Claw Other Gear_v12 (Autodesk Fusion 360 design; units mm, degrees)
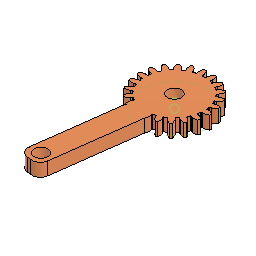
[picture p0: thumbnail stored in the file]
description: Spur Gear; Module: 0.7; Num Teeth: 22; Pressure Angle: 20.0; Backlash: 0.00 mm
sketch "Sketch1" plane through (0, 0, 0) normal (0, 0, 1) x axis (1, 0, 0)
  circle C1 centre (0, 0) radius 6.8092
  circle C2 centre (0, 0) radius 1.6
  dimension "d104" diameter C2 = 3.2
extrude "Extrude1" new body sketch "Sketch1" along normal blind 3
sketch "Sketch2" plane through (0, 0, 0) normal (0, 0, 1) x axis (1, 0, 0)
  curve K1 (8.3964, -0.2471) -> (7.2087, -0.6237)
  curve K2 (8.3964, 0.2471) -> (7.2087, 0.6237)
  line L1 (7.2087, -0.6237) -> (6.7739, -0.5869)
  line L2 (7.2087, 0.6237) -> (6.7739, 0.5869)
  line L3 (6.7739, 0.5869) -> (6.7739, -0.5869)
  arc A1 centre (0, 0) radius 8.4 clockwise from (8.3964, 0.2471) to (8.3964, -0.2471)
extrude "Extrude2" add sketch "Sketch2" along normal blind 3
fillet "Fillet1" radius 0.1
circular_pattern "C-Pattern1" countU 22 TotalAngle 360
sketch "Sketch3" plane through (0, 0, 0) normal (0, 0, 1) x axis (1, 0, 0)
  circle C1 centre (0, 0) radius 7.7
sketch "Sketch5" plane through (0, 0, 3) normal (0, 0, 1) x axis (-1, 0, 0)
  line L1 (-7.2087, 0.6237) -> (-6.8825, 0.5961)
  curve K1 (-8.3964, 0.2471) -> (-7.2087, 0.6237)
  curve K2 (-7.2087, -0.6237) -> (-8.3964, -0.2471)
  line L2 (-6.8825, -0.5961) -> (-7.2087, -0.6237)
  line L3 (-7.0924, -1.4325) -> (-6.7717, -1.3671)
  curve K3 (-8.1259, -2.1285) -> (-7.0924, -1.4325)
  curve K4 (-6.741, -2.6294) -> (-7.9866, -2.6026)
  line L4 (-6.4358, -2.511) -> (-6.741, -2.6294)
  line L5 (-6.4015, -3.3726) -> (-6.1122, -3.2195)
  curve K5 (-7.197, -4.3316) -> (-6.4015, -3.3726)
  curve K6 (-5.7272, -4.422) -> (-6.9299, -4.7473)
  line L6 (-5.4676, -4.2224) -> (-5.7272, -4.422)
  line L7 (-5.1921, -5.0395) -> (-4.9576, -4.8111)
  curve K7 (-5.6852, -6.1838) -> (-5.1921, -5.0395)
  curve K8 (-4.2493, -5.8564) -> (-5.3117, -6.5073)
  line L8 (-4.0566, -5.5918) -> (-4.2493, -5.8564)
  line L9 (-3.5619, -6.2982) -> (-3.4013, -6.0129)
  curve K9 (-3.7127, -7.535) -> (-3.5619, -6.2982)
  curve K10 (-2.4273, -6.8164) -> (-3.2632, -7.7402)
  line L10 (-2.3168, -6.5082) -> (-2.4273, -6.8164)
  line L11 (-1.6432, -7.0466) -> (-1.5695, -6.7276)
  curve K11 (-1.4395, -8.2757) -> (-1.6432, -7.0466)
  curve K12 (-0.4086, -7.2241) -> (-0.9504, -8.3461)
  line L12 (-0.3894, -6.8973) -> (-0.4086, -7.2241)
  line L13 (0.4086, -7.2241) -> (0.3894, -6.8973)
  curve K13 (0.9504, -8.3461) -> (0.4086, -7.2241)
  curve K14 (1.6432, -7.0466) -> (1.4395, -8.2757)
  line L14 (1.5695, -6.7276) -> (1.6432, -7.0466)
  line L15 (2.4273, -6.8164) -> (2.3168, -6.5082)
  curve K15 (3.2632, -7.7402) -> (2.4273, -6.8164)
  curve K16 (3.5619, -6.2982) -> (3.7127, -7.535)
  line L16 (3.4013, -6.0129) -> (3.5619, -6.2982)
  line L17 (4.2493, -5.8564) -> (4.0566, -5.5918)
  curve K17 (5.3117, -6.5073) -> (4.2493, -5.8564)
  curve K18 (5.1921, -5.0395) -> (5.6852, -6.1838)
  line L18 (4.9576, -4.8111) -> (5.1921, -5.0395)
  line L19 (5.7272, -4.422) -> (5.4676, -4.2224)
  curve K19 (6.9299, -4.7473) -> (5.7272, -4.422)
  curve K20 (6.4015, -3.3726) -> (7.197, -4.3316)
  line L20 (6.1122, -3.2195) -> (6.4015, -3.3726)
  line L21 (6.741, -2.6294) -> (6.4358, -2.511)
  curve K21 (7.9866, -2.6026) -> (6.741, -2.6294)
  curve K22 (7.0924, -1.4325) -> (8.1259, -2.1285)
  line L22 (6.7717, -1.3671) -> (7.0924, -1.4325)
  line L23 (7.2087, -0.6237) -> (6.8825, -0.5961)
  curve K23 (8.3964, -0.2471) -> (7.2087, -0.6237)
  curve K24 (7.2087, 0.6237) -> (8.3964, 0.2471)
  line L24 (6.8825, 0.5961) -> (7.2087, 0.6237)
  line L25 (7.0924, 1.4325) -> (6.7717, 1.3671)
  curve K25 (8.1259, 2.1285) -> (7.0924, 1.4325)
  curve K26 (6.741, 2.6294) -> (7.9866, 2.6026)
  line L26 (6.4358, 2.511) -> (6.741, 2.6294)
  line L27 (6.4015, 3.3726) -> (6.1122, 3.2195)
  curve K27 (7.197, 4.3316) -> (6.4015, 3.3726)
  curve K28 (5.7272, 4.422) -> (6.9299, 4.7473)
  line L28 (5.4676, 4.2224) -> (5.7272, 4.422)
  line L29 (5.1921, 5.0395) -> (4.9576, 4.8111)
  curve K29 (5.6852, 6.1838) -> (5.1921, 5.0395)
  curve K30 (4.2493, 5.8564) -> (5.3117, 6.5073)
  line L30 (4.0566, 5.5918) -> (4.2493, 5.8564)
  line L31 (3.5619, 6.2982) -> (3.4013, 6.0129)
  curve K31 (3.7127, 7.535) -> (3.5619, 6.2982)
  curve K32 (2.4273, 6.8164) -> (3.2632, 7.7402)
  line L32 (2.3168, 6.5082) -> (2.4273, 6.8164)
  line L33 (1.6432, 7.0466) -> (1.5695, 6.7276)
  curve K33 (1.4395, 8.2757) -> (1.6432, 7.0466)
  curve K34 (0.4086, 7.2241) -> (0.9504, 8.3461)
  line L34 (0.3894, 6.8973) -> (0.4086, 7.2241)
  line L35 (-0.4086, 7.2241) -> (-0.3894, 6.8973)
  curve K35 (-0.9504, 8.3461) -> (-0.4086, 7.2241)
  curve K36 (-1.6432, 7.0466) -> (-1.4395, 8.2757)
  line L36 (-1.5695, 6.7276) -> (-1.6432, 7.0466)
  line L37 (-2.4273, 6.8164) -> (-2.3168, 6.5082)
  curve K37 (-3.2632, 7.7402) -> (-2.4273, 6.8164)
  curve K38 (-3.5619, 6.2982) -> (-3.7127, 7.535)
  line L38 (-3.4013, 6.0129) -> (-3.5619, 6.2982)
  line L39 (-4.2493, 5.8564) -> (-4.0566, 5.5918)
  curve K39 (-5.3117, 6.5073) -> (-4.2493, 5.8564)
  curve K40 (-5.1921, 5.0395) -> (-5.6852, 6.1838)
  line L40 (-4.9576, 4.8111) -> (-5.1921, 5.0395)
  line L41 (-5.7272, 4.422) -> (-5.4676, 4.2224)
  curve K41 (-6.9299, 4.7473) -> (-5.7272, 4.422)
  curve K42 (-6.4015, 3.3726) -> (-7.197, 4.3316)
  line L42 (-6.1122, 3.2195) -> (-6.4015, 3.3726)
  line L43 (-6.741, 2.6294) -> (-6.4358, 2.511)
  curve K43 (-7.9866, 2.6026) -> (-6.741, 2.6294)
  curve K44 (-7.0924, 1.4325) -> (-8.1259, 2.1285)
  line L44 (-6.7717, 1.3671) -> (-7.0924, 1.4325)
  line L45 (-1.6, 0) -> (0, 0)
  line L46 (-2.4786, 0.3263) -> (0, 0)
  line L47 (2.4786, -0.3263) -> (-2.4786, 0.3263)
  line L48 (6.3944, 29.417) -> (2.4786, -0.3263)
  line L49 (1.4372, 30.0697) -> (6.3944, 29.417)
  line L50 (-2.4786, 0.3263) -> (1.4372, 30.0697)
  line L51 (3.4058, 25.8698) -> (3.9158, 29.7433)
  arc A1 centre (0, 0) radius 6.8092 clockwise from (-6.7746, 0.6857) to (-6.6934, 1.2507)
  arc A2 centre (-6.8741, 0.6958) radius 0.1 clockwise from (-6.7746, 0.6857) to (-6.8825, 0.5961)
  arc A3 centre (0, 0) radius 8.4 clockwise from (-8.3964, -0.2471) to (-8.3964, 0.2471)
  arc A4 centre (-6.8741, -0.6958) radius 0.1 clockwise from (-6.8825, -0.5961) to (-6.7746, -0.6857)
  arc A5 centre (0, 0) radius 6.8092 clockwise from (-6.6934, -1.2507) to (-6.7746, -0.6857)
  arc A6 centre (-6.7916, -1.2691) radius 0.1 clockwise from (-6.6934, -1.2507) to (-6.7717, -1.3671)
  arc A7 centre (0, 0) radius 8.4 clockwise from (-7.9866, -2.6026) to (-8.1259, -2.1285)
  arc A8 centre (-6.3996, -2.6042) radius 0.1 clockwise from (-6.4358, -2.511) to (-6.307, -2.5665)
  arc A9 centre (0, 0) radius 6.8092 clockwise from (-6.0699, -3.0858) to (-6.307, -2.5665)
  arc A10 centre (-6.159, -3.1311) radius 0.1 clockwise from (-6.0699, -3.0858) to (-6.1122, -3.2195)
  arc A11 centre (0, 0) radius 8.4 clockwise from (-6.9299, -4.7473) to (-7.197, -4.3316)
  arc A12 centre (-5.4067, -4.3017) radius 0.1 clockwise from (-5.4676, -4.2224) to (-5.3284, -4.2395)
  arc A13 centre (0, 0) radius 6.8092 clockwise from (-4.9546, -4.6709) to (-5.3284, -4.2395)
  arc A14 centre (-5.0274, -4.7395) radius 0.1 clockwise from (-4.9546, -4.6709) to (-4.9576, -4.8111)
  arc A15 centre (0, 0) radius 8.4 clockwise from (-5.3117, -6.5073) to (-5.6852, -6.1838)
  arc A16 centre (-3.9757, -5.6507) radius 0.1 clockwise from (-4.0566, -5.5918) to (-3.9182, -5.5689)
  arc A17 centre (0, 0) radius 6.8092 clockwise from (-3.438, -5.8775) to (-3.9182, -5.5689)
  arc A18 centre (-3.4885, -5.9639) radius 0.1 clockwise from (-3.438, -5.8775) to (-3.4013, -6.0129)
  arc A19 centre (0, 0) radius 8.4 clockwise from (-3.2632, -7.7402) to (-3.7127, -7.535)
  arc A20 centre (-2.2227, -6.5419) radius 0.1 clockwise from (-2.3168, -6.5082) to (-2.1905, -6.4472)
  arc A21 centre (0, 0) radius 6.8092 clockwise from (-1.6428, -6.608) to (-2.1905, -6.4472)
  arc A22 centre (-1.667, -6.7051) radius 0.1 clockwise from (-1.6428, -6.608) to (-1.5695, -6.7276)
  arc A23 centre (0, 0) radius 8.4 clockwise from (-0.9504, -8.3461) to (-1.4395, -8.2757)
  arc A24 centre (-0.2896, -6.9031) radius 0.1 clockwise from (-0.3894, -6.8973) to (-0.2854, -6.8032)
  arc A25 centre (0, 0) radius 6.8092 clockwise from (0.2854, -6.8032) to (-0.2854, -6.8032)
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  point P1 (0, 0)
  point P223 (0, 0)
  point P4 (0, 0)
  point P225 (0, 0)
  point P230 (3.9158, 29.7433)
  point P232 (3.5895, 27.2647)
  point P226 (-2.4786, 0.3263)
  point P229 (1.4372, 30.0697)
  coincident P1 P223
  horizontal L45
  coincident P4 P225
  perpendicular L47 L48
  parallel L47 L49
  parallel L48 L50
  parallel L46 L47
  midpoint L49 P230
  perpendicular L49 L51
  coincident L51 P232
  dimension "d83" distance P225 P226 = 2.5
  dimension "d84" angle L45 L46 = 172.5 (= "180 deg - 7.5 deg")
  dimension "d97" distance P226 P229 = 30
  dimension "d98" diameter = 3.2
  dimension "d99" distance L49 P232 = 2.5
extrude "Extrude7" add sketch "Sketch5" against normal blind 3
fillet "Fillet4" radius 2
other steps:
create_component "CreateComponent4"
